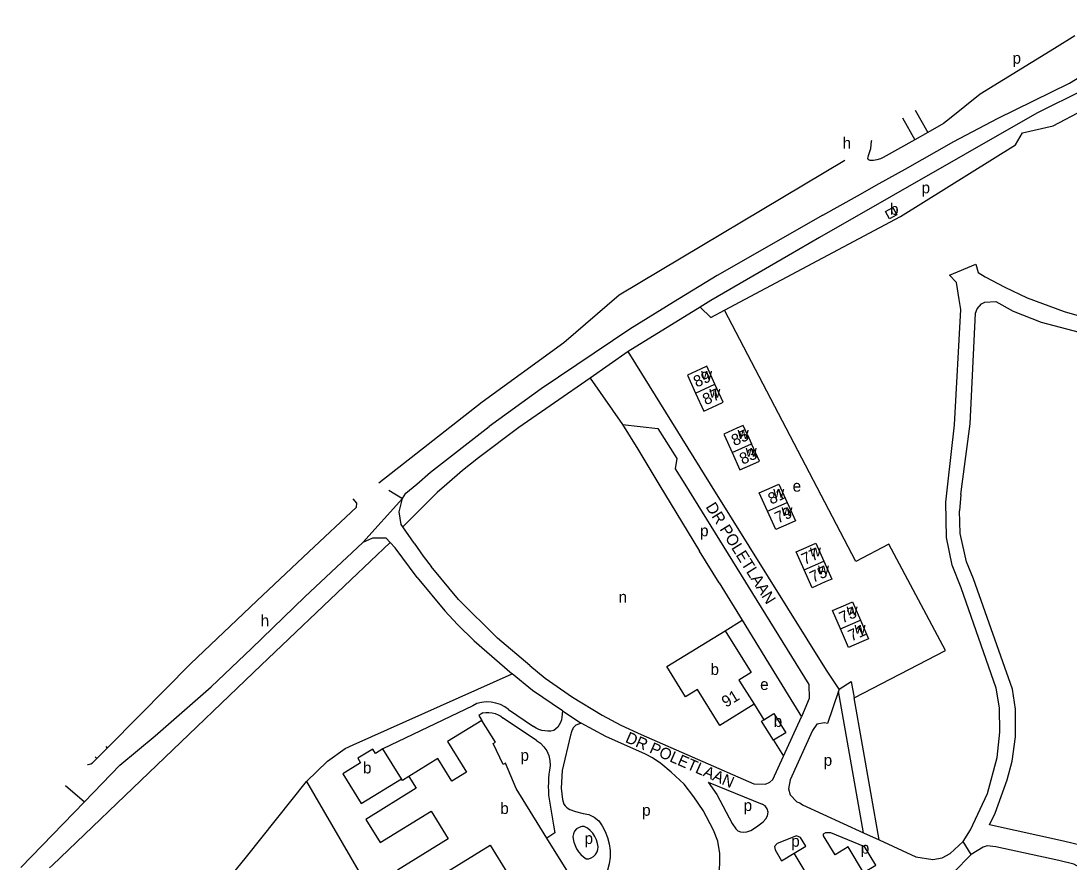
# Model space of a CAD drawing. Extents: x 158142 to 159655, y 385262 to 387204.
# Drawn here: x 158355.3 to 158722.6, y 386850.2 to 387145.1 of the extents above; entities that cross this region are included whole.
import ezdxf

# ---------------------------------------------------------------- set-up
doc = ezdxf.new("R2010")
doc.units = 0
for name, color, linetype in [('BLT_Basislijn', 7, 'Continuous'), ('BLT_Bebouwing', 7, 'Continuous'), ('BLT_Centroide', 7, 'Continuous'), ('BLT_Huisnummer', 7, 'Continuous'), ('BLT_Onderverdeling_panden', 7, 'Continuous'), ('BLT_Straatnaam_verkleind', 7, 'Continuous'), ('BLT_Vlakafsluiter', 7, 'Continuous')]:
    doc.layers.add(name, color=color, linetype=linetype)

msp = doc.modelspace()

# ---------------------------------------------------------------- linework, layer by layer
at = {"layer": 'BLT_Basislijn'}
for p, q in [((158668.7, 387113.83), (158673.07, 387105.98)), ((158664.2, 387111.11), (158668.54, 387103.46)), ((158668.54, 387103.46), (158657.46, 387097.25)), ((158624.3, 387062.87), (158597.06, 387047.07)), ((158597.06, 387047.07), (158593.31, 387044.75)), ((158593.31, 387044.75), (158568.1, 387029.18)), ((158647.81, 386955.65), (158601.87, 387043.7)), ((158568.1, 387029.18), (158554.76, 387019.92)), ((158575.58, 387017.14), (158568.1, 387029.18)), ((158554.76, 387019.92), (158529.78, 387002.58)), ((158554.76, 387019.92), (158566.14, 387003.6)), ((158596.96, 386982.75), (158575.58, 387017.14)), ((158566.14, 387003.6), (158578.5, 387002.22)), ((158566.14, 387003.6), (158571.44, 386995.01)), ((158571.44, 386995.01), (158578.85, 386982.75)), ((158578.85, 386982.75), (158593.07, 386959.23)), ((158684.65, 386979.06), (158685.14, 386982.75)), ((158684.65, 386979.06), (158684.23, 386973.41)), ((158493.12, 386962.04), (158489.16, 386967.74)), ((158599.96, 386948.18), (158593.07, 386959.23)), ((158599.96, 386948.18), (158608.05, 386934.99)), ((158602.06, 386931.34), (158608.05, 386934.99)), ((158608.05, 386934.99), (158617.27, 386919.95)), ((158617.27, 386919.95), (158628.83, 386901.11)), ((158641.77, 386910.13), (158637.96, 386898.8)), ((158642.03, 386910.9), (158641.77, 386910.13)), ((158650.51, 386860.51), (158641.77, 386910.13)), ((158656.03, 386857.97), (158647.27, 386907.76)), ((158612.17, 386905.54), (158615.56, 386900.12)), ((158396.89, 386901.68), (158385.54, 386890.21)), ((158517.13, 386902.5), (158515.7, 386901.64)), ((158515.7, 386901.64), (158516.78, 386899.9)), ((158535.92, 386892.82), (158524.32, 386900.73)), ((158526.18, 386903.69), (158534.91, 386897.78)), ((158545, 386903.25), (158551.64, 386898.89)), ((158622.54, 386887.32), (158628.83, 386901.11)), ((158549.76, 386898.23), (158548.84, 386897.27)), ((158551.64, 386898.89), (158549.76, 386898.23)), ((158547.87, 386894.73), (158544.99, 386882.31)), ((158619.04, 386892.93), (158622.54, 386887.32)), ((158385.54, 386890.21), (158381.83, 386886.51)), ((158385.06, 386890.71), (158385.54, 386890.21)), ((158381.28, 386887.07), (158381.83, 386886.51)), ((158381.53, 386886.17), (158381.5, 386886.13)), ((158544.99, 386882.31), (158544.6, 386876.15)), ((158455.35, 386878.49), (158485.3, 386827.07)), ((158596.09, 386878.27), (158614.99, 386870.5)), ((158544.6, 386876.15), (158545.01, 386872.12)), ((158540.34, 386872.23), (158541.91, 386863.19)), ((158545.01, 386872.12), (158545.49, 386870.48)), ((158549.63, 386867.99), (158552.28, 386867.28)), ((158542.39, 386860.42), (158539.56, 386858.66)), ((158638.94, 386860.64), (158650.86, 386855.74)), ((158650.51, 386860.51), (158656.03, 386857.97)), ((158654.05, 386807.61), (158626.22, 386853.36))]:
    msp.add_line(p, q, dxfattribs=at)
for points in [[(158656.08, 387088.12), (158665.09, 387093.2), (158682.14, 387102.8), (158697.48, 387110.9), (158722.77, 387123.25), (158758.56, 387145.1)], [(158724.65, 387139.9), (158717.53, 387135.44), (158691.44, 387119.47), (158680.62, 387110.78), (158678.6, 387109.21), (158673.07, 387105.98)], [(158601.87, 387043.7), (158663.51, 387076.57), (158703.82, 387101.71), (158706.29, 387105.85), (158716.99, 387108.3), (158738.31, 387119.52), (158746.24, 387131.78)], [(158746.24, 387131.78), (158727.74, 387120.92), (158711.33, 387112.82), (158635.07, 387069.15)], [(158673.07, 387105.98), (158668.54, 387103.46)], [(158657.46, 387097.25), (158656.47, 387096.81), (158655.24, 387096.42), (158654.08, 387096.24), (158652.87, 387096.21), (158652.47, 387096.33), (158652.21, 387096.58), (158652.08, 387096.94), (158652.14, 387097.34), (158652.31, 387097.95), (158653.07, 387100.38), (158653.35, 387102.91), (158653.48, 387103.32)], [(158480.68, 386983.16), (158516.92, 387011.54), (158545.57, 387032.33), (158564.97, 387049.05), (158644.03, 387096.29)], [(158636.25, 387077.06), (158648.47, 387083.82), (158656.08, 387088.12)], [(158636.25, 387077.06), (158599.31, 387055.86)], [(158635.07, 387069.15), (158624.3, 387062.87)], [(158680.15, 386982.75), (158682.46, 387003.56), (158684.6, 387043.95), (158684.07, 387047.47), (158683.08, 387053.45), (158680.71, 387055.94), (158689.96, 387059.86)], [(158689.96, 387059.86), (158690.74, 387056.94), (158693.14, 387055.45), (158700.11, 387051.72), (158707.9, 387047.99), (158720.81, 387043.24), (158746.32, 387035.84), (158759.77, 387029.16), (158763.61, 387026.95), (158774.11, 387016.37)], [(158599.31, 387055.86), (158583.99, 387046.46)], [(158583.99, 387046.46), (158568.67, 387037.06), (158537.53, 387016.18), (158519.39, 387002.88)], [(158593.31, 387044.75), (158597.05, 387041.13), (158601.87, 387043.7)], [(158685.14, 386982.75), (158687.96, 387003.81), (158689.75, 387042.71), (158690.33, 387044.22), (158691.93, 387045.94), (158693.02, 387046.57), (158696.92, 387046.72), (158702.97, 387043.35), (158712.86, 387039.5), (158730.6, 387034.84), (158745.14, 387030.27), (158755.08, 387025.45), (158760.74, 387022.19), (158771.37, 387011.13)], [(158493.99, 386982.75), (158498.83, 386986.91), (158519.39, 387002.88)], [(158529.78, 387002.58), (158515.61, 386991.9), (158510.02, 386987.52), (158504.51, 386982.75)], [(158578.5, 387002.22), (158585.12, 386991.69), (158584.58, 386988.13), (158587.91, 386982.75)], [(158489.01, 386977.69), (158490.21, 386979.51), (158493.99, 386982.75)], [(158504.51, 386982.75), (158501.1, 386979.81), (158489.16, 386967.74)], [(158587.91, 386982.75), (158631.34, 386912.43), (158631.5, 386907.6), (158628.83, 386901.11)], [(158642.03, 386910.9), (158637.55, 386917.48), (158596.96, 386982.75)], [(158685.49, 386857.44), (158688.04, 386861.5), (158693.99, 386874.3), (158697.34, 386886.83), (158698.37, 386895.73), (158698.24, 386904.35), (158697.02, 386911.16), (158684.72, 386946.4), (158681.66, 386954.26), (158679.6, 386964.01), (158679.44, 386976.41), (158680.15, 386982.75)], [(158396.89, 386901.68), (158414.75, 386919.69), (158437.92, 386941.81), (158456.13, 386958.95), (158472.85, 386974.67), (158472.97, 386976.09), (158471.68, 386977.52)], [(158489.16, 386967.74), (158488.55, 386968.62), (158487.8, 386973), (158489.01, 386977.69)], [(158694.72, 386863.26), (158696.7, 386867.43), (158700.85, 386879.03), (158702.59, 386885.55), (158703.78, 386894.19), (158703.78, 386903.86), (158702.74, 386910.84), (158689.07, 386949.52), (158686.68, 386955.53), (158684.46, 386965.39), (158684.23, 386973.41)], [(158484.7, 386962.23), (158483.26, 386963.74), (158478.42, 386963.74), (158475.1, 386962.23)], [(158365.31, 386848.23), (158366.35, 386849.16), (158439.42, 386919.27), (158470.86, 386949.22), (158484.7, 386962.23)], [(158475.1, 386962.23), (158454.77, 386943.25)], [(158494.09, 386949.99), (158486.47, 386960.37), (158484.7, 386962.23)], [(158493.12, 386962.04), (158496.21, 386957.48), (158499.01, 386953.89)], [(158647.27, 386907.76), (158679.26, 386924.45), (158659.44, 386961.72), (158647.81, 386955.65)], [(158533.64, 386919.09), (158522.24, 386928.72), (158508.56, 386942.27), (158499.01, 386953.89)], [(158494.09, 386949.99), (158503.8, 386938.26), (158508.25, 386933.49), (158514.13, 386927.76), (158527.41, 386916.22)], [(158389.95, 386884.22), (158402.29, 386894.48), (158421.96, 386911.72), (158436.04, 386925.08), (158454.77, 386943.25)], [(158533.64, 386919.09), (158538.97, 386914.68), (158548.56, 386908.02), (158559, 386901.74), (158565.5, 386898.28), (158572.62, 386894.91), (158612.16, 386877.6), (158616.23, 386877.57), (158617.73, 386878.24), (158618.79, 386879.12), (158622.54, 386887.32)], [(158455.35, 386878.49), (158462.68, 386885.65), (158468.94, 386889.99), (158471.67, 386891.38), (158527.41, 386916.22)], [(158545, 386903.25), (158534.49, 386910.36), (158527.41, 386916.22)], [(158642.03, 386910.9), (158646.26, 386913.48), (158647.27, 386907.76)], [(158515.06, 386905.84), (158513.61, 386905.01), (158482.13, 386889.9)], [(158526.18, 386903.69), (158524.84, 386904.64), (158523.35, 386905.42), (158521.73, 386905.98), (158520.04, 386906.31), (158518.33, 386906.39), (158516.66, 386906.22), (158515.06, 386905.84)], [(158517.13, 386902.5), (158518.19, 386902.65), (158519.29, 386902.67), (158520.39, 386902.55), (158521.46, 386902.28), (158522.5, 386901.88), (158523.46, 386901.36), (158524.32, 386900.73)], [(158545, 386903.25), (158544.85, 386901.02), (158544.66, 386900.1), (158544.35, 386899.2), (158543.91, 386898.35), (158543.37, 386897.57), (158542.73, 386896.88), (158542.02, 386896.3)], [(158542.02, 386896.3), (158540.99, 386896.14), (158539.92, 386896.1), (158538.84, 386896.19), (158537.78, 386896.41), (158536.76, 386896.76), (158535.8, 386897.22), (158534.91, 386897.78)], [(158548.84, 386897.27), (158548.66, 386896.92), (158548.5, 386896.57), (158548.35, 386896.21), (158548.21, 386895.85), (158548.08, 386895.48), (158547.97, 386895.11), (158547.87, 386894.73)], [(158574.2, 386888.04), (158560.19, 386894.3), (158551.64, 386898.89)], [(158637.96, 386898.8), (158636.82, 386899.03), (158634.2, 386898.53), (158632.68, 386896.3), (158624.82, 386879.03), (158624.29, 386875.85), (158624.85, 386873.77), (158627.12, 386871.37), (158628.24, 386871.05), (158629.19, 386870.32), (158650.51, 386860.51)], [(158535.92, 386892.82), (158537.29, 386891.88), (158538.51, 386890.67), (158539.52, 386889.21), (158540.24, 386887.57), (158540.64, 386885.85), (158540.72, 386884.12), (158540.49, 386882.48)], [(158378.6, 386884.49), (158378.88, 386884.49), (158379.82, 386884.69), (158380.39, 386885.02), (158381.09, 386885.67), (158381.83, 386886.51)], [(158588.55, 386827.21), (158591.7, 386830.27), (158595.11, 386834.66), (158597.78, 386839.54), (158599.8, 386845.67), (158600.25, 386849.45), (158600.15, 386853.26), (158599.44, 386857.59), (158598, 386861.47), (158594.4, 386868.25), (158591.12, 386873.15), (158587.7, 386877.49), (158583.18, 386881.78), (158579.53, 386884.75), (158576.62, 386886.78), (158574.2, 386888.04)], [(158389.95, 386884.22), (158377.52, 386871.37)], [(158540.49, 386882.48), (158540.31, 386881.03), (158540.17, 386879.57), (158540.1, 386878.1), (158540.07, 386876.63), (158540.11, 386875.16), (158540.2, 386873.69), (158540.34, 386872.23)], [(158405.76, 386799.46), (158404, 386805.94), (158403.45, 386811.11), (158403.75, 386814.36), (158434.32, 386852.05), (158455.35, 386878.49)], [(158491.24, 386880.18), (158489.01, 386878.8), (158488.6, 386879.46)], [(158596.09, 386878.27), (158599.15, 386873.86), (158604.54, 386863.74), (158605.8, 386861.86), (158606.55, 386861.22), (158607.47, 386860.87), (158608.45, 386860.7), (158609.65, 386860.82), (158611.08, 386861.32), (158613.09, 386862.56), (158615.33, 386864.37), (158616.31, 386865.39), (158616.91, 386866.48), (158617.12, 386867.71), (158616.76, 386868.9), (158616.03, 386869.91), (158614.99, 386870.5)], [(158377.52, 386871.37), (158355.28, 386848.37)], [(158545.49, 386870.48), (158545.94, 386869.95), (158546.46, 386869.47), (158547.02, 386869.04), (158547.64, 386868.67), (158548.28, 386868.37), (158548.95, 386868.15), (158549.63, 386867.99)], [(158552.28, 386867.28), (158554.27, 386866.9), (158556.16, 386866), (158557.76, 386864.64), (158558.91, 386862.97)], [(158552.28, 386867.28), (158554.27, 386866.9), (158556.16, 386866), (158557.76, 386864.64), (158558.91, 386862.97)], [(158552.28, 386867.28), (158554.27, 386866.9), (158556.16, 386866), (158557.76, 386864.64), (158558.91, 386862.97)], [(158552.28, 386867.28), (158554.27, 386866.9), (158556.16, 386866), (158557.76, 386864.64), (158558.91, 386862.97)], [(158541.91, 386863.19), (158542.39, 386860.42)], [(158552.66, 386862.65), (158551.79, 386862.64), (158550.86, 386862.38), (158550, 386861.85), (158549.3, 386861.08), (158548.86, 386860.16), (158548.7, 386859.22), (158548.78, 386858.35)], [(158557.57, 386855.54), (158557.38, 386856.79), (158557, 386858.03), (158556.43, 386859.21), (158555.69, 386860.31), (158554.79, 386861.28), (158553.78, 386862.09), (158552.66, 386862.65)], [(158558.91, 386862.97), (158559.99, 386860.98), (158560.84, 386858.83), (158561.41, 386856.57), (158561.71, 386854.24), (158561.71, 386851.91), (158561.43, 386849.62), (158560.88, 386847.42)], [(158650.56, 386846.6), (158645.11, 386855.54), (158640.56, 386852.77), (158636.49, 386859.45), (158636.56, 386860.12), (158637.37, 386860.61), (158638.94, 386860.64)], [(158740.75, 386841.06), (158733.89, 386850.93), (158730.75, 386853.84), (158726.94, 386856.05), (158720.61, 386857.61), (158694.72, 386863.26)], [(158548.78, 386858.35), (158549.05, 386857.17), (158549.47, 386856.01), (158550.02, 386854.9), (158550.7, 386853.85), (158551.49, 386852.9), (158552.38, 386852.05), (158553.35, 386851.32)], [(158656.03, 386857.97), (158668.93, 386852.03), (158674.82, 386851.13), (158678.1, 386851.74), (158680.96, 386853.27), (158685.49, 386857.44)], [(158553.35, 386851.32), (158554.23, 386851.41), (158555.12, 386851.71), (158555.96, 386852.22), (158556.67, 386852.93), (158557.18, 386853.76), (158557.48, 386854.66), (158557.57, 386855.54)], [(158650.56, 386846.6), (158654.84, 386849.2), (158650.86, 386855.74)], [(158693.92, 386823.99), (158682.07, 386843.09), (158681.86, 386843.92), (158682.12, 386846.62), (158688.28, 386852.84)], [(158731.6, 386841.96), (158728.58, 386846.31), (158726.56, 386848.18), (158724.3, 386849.49), (158719.03, 386850.79), (158696.95, 386855.61), (158693.92, 386855.92), (158692.49, 386855.5), (158688.28, 386852.84)]]:
    msp.add_lwpolyline(points, dxfattribs=at)
msp.add_lwpolyline([(158626.22, 386853.36), (158630.31, 386855.85), (158628.46, 386858.89), (158627.1, 386859.46), (158620.24, 386856.69), (158619.39, 386855.68), (158619.56, 386854.52), (158621.82, 386850.68)], close=True, dxfattribs=at)
at = {"layer": 'BLT_Bebouwing'}
for p, q in [((158601.7, 387000), (158604.46, 386993.84)), ((158609.91, 387000), (158611.3, 386996.91)), ((158602.06, 386931.34), (158611.12, 386916.66)), ((158607.12, 386913.62), (158612.17, 386905.54)), ((158614.85, 386899.68), (158615.56, 386900.12)), ((158619.04, 386892.93), (158614.85, 386899.68))]:
    msp.add_line(p, q, dxfattribs=at)
msp.add_lwpolyline([(158660.81, 387079.73), (158662.26, 387077.17), (158659.69, 387075.72), (158658.24, 387078.28)], close=True, dxfattribs=at)
for points in [[(158598.45, 387017.74), (158595.58, 387024.04), (158593.37, 387023.03), (158588.82, 387020.95), (158591.69, 387014.66)], [(158591.69, 387014.66), (158594.56, 387008.36), (158599.11, 387010.44), (158601.33, 387011.45), (158598.45, 387017.74)], [(158609.91, 387000), (158608.42, 387003.33), (158606.14, 387002.31), (158601.58, 387000.26), (158601.7, 387000)], [(158604.46, 386993.84), (158607.22, 386987.69), (158611.78, 386989.73), (158614.06, 386990.75), (158611.3, 386996.91)], [(158616.9, 386973.22), (158614.02, 386979.67), (158618.58, 386981.71), (158620.92, 386982.75), (158623.8, 386976.31)], [(158623.8, 386976.31), (158626.68, 386969.87), (158624.35, 386968.82), (158619.78, 386966.78), (158616.9, 386973.22)], [(158629.74, 386952.68), (158626.92, 386958.98), (158631.48, 386961.02), (158633.78, 386962.05), (158636.6, 386955.75)], [(158636.6, 386955.75), (158639.43, 386949.45), (158637.13, 386948.42), (158632.57, 386946.38), (158629.74, 386952.68)], [(158642.5, 386931.99), (158639.73, 386938.48), (158644.33, 386940.45), (158646.74, 386941.48), (158649.51, 386934.98)], [(158649.51, 386934.98), (158652.28, 386928.48), (158649.87, 386927.45), (158645.27, 386925.49), (158642.5, 386931.99)], [(158592.41, 386910.77), (158588.18, 386908.2), (158581.66, 386918.75), (158602.06, 386931.34)], [(158611.12, 386916.66), (158606.87, 386914.04), (158607.12, 386913.62)], [(158612.17, 386905.54), (158600.2, 386898.15), (158592.41, 386910.77)], [(158615.56, 386900.12), (158619.1, 386902.32), (158623.29, 386895.56), (158619.04, 386892.93)], [(158516.78, 386899.9), (158504.75, 386892.44), (158511.36, 386881.78), (158506.27, 386878.62), (158501.39, 386886.48), (158491.24, 386880.18)], [(158539.56, 386858.66), (158528.79, 386876.02), (158525.08, 386884.85), (158524.26, 386884.42), (158520.74, 386891.76), (158521.52, 386892.26), (158516.78, 386899.9)], [(158482.13, 386889.9), (158479.52, 386888.28), (158478.55, 386889.85), (158473.33, 386886.61), (158474.3, 386885.05), (158468.04, 386881.16)], [(158488.6, 386879.46), (158482.13, 386889.9)], [(158468.04, 386881.16), (158474.51, 386870.73), (158488.6, 386879.46)], [(158491.24, 386880.18), (158493.79, 386876.08), (158476.17, 386865.15), (158481.2, 386857.05), (158498.99, 386868.08), (158505.02, 386858.34), (158487.29, 386847.34), (158492.27, 386839.2), (158519.66, 386856.18), (158525.88, 386846.15), (158517.48, 386840.94), (158526.73, 386826.02)], [(158570.34, 386833.65), (158560.86, 386840.39), (158553.66, 386835.92), (158539.56, 386858.66)]]:
    msp.add_lwpolyline(points, dxfattribs=at)
at = {"layer": 'BLT_Onderverdeling_panden'}
for p, q in [((158591.69, 387014.66), (158598.45, 387017.74)), ((158604.46, 386993.84), (158611.3, 386996.91)), ((158616.9, 386973.22), (158623.8, 386976.31)), ((158629.74, 386952.68), (158636.6, 386955.75)), ((158642.5, 386931.99), (158649.51, 386934.98))]:
    msp.add_line(p, q, dxfattribs=at)
at = {"layer": 'BLT_Vlakafsluiter'}
for p, q in [((158475.1, 386962.23), (158489.01, 386977.69)), ((158484.18, 386980.66), (158489.01, 386977.69)), ((158370.89, 386877.07), (158377.52, 386871.37)), ((158688.28, 386852.84), (158685.49, 386857.44))]:
    msp.add_line(p, q, dxfattribs=at)

# ---------------------------------------------------------------- texts
at = {"layer": 'BLT_Centroide'}
for s, p in [('p', (158702.75, 387130.11)), ('h', (158643.23, 387100.3)), ('p', (158670.88, 387084.67)), ('b', (158659.85, 387077.16)), ('w', (158593.63, 387019.34)), ('w', (158596.51, 387013.06)), ('w', (158606.44, 386998.59)), ('w', (158609.26, 386992.31)), ('w', (158618.91, 386978)), ('e', (158625.71, 386980.08)), ('w', (158621.8, 386971.53)), ('p', (158593.27, 386964.44)), ('w', (158631.76, 386957.38)), ('w', (158634.59, 386951.06)), ('n', (158564.69, 386941.16)), ('h', (158439.29, 386932.91)), ('w', (158644.62, 386936.72)), ('w', (158647.39, 386930.25)), ('b', (158596.92, 386915.81)), ('e', (158614.32, 386910.56)), ('b', (158619.08, 386897.62)), ('b', (158475.13, 386881.31)), ('p', (158530.33, 386885.71)), ('p', (158636.59, 386883.97)), ('b', (158523.25, 386867.08)), ('p', (158608.54, 386868.14)), ('p', (158572.96, 386866.46)), ('p', (158552.77, 386856.57)), ('p', (158625.21, 386855.6)), ('p', (158649.59, 386853.19))]:
    msp.add_text(s, height=4, dxfattribs=at).set_placement(p)
at = {"layer": 'BLT_Huisnummer'}
for s, rotation, p in [('89', 24.5302, (158592.06, 387016.54)), ('87', 24.5302, (158595.27, 387010.34)), ('85', 24.5302, (158605.33, 386995.98)), ('83', 24.5302, (158608.21, 386989.48)), ('81', 24.5302, (158618.19, 386975.5)), ('79', 24.5302, (158620.56, 386968.87)), ('77', 24.5302, (158629.89, 386954.35)), ('75', 24.5302, (158632.84, 386948.08)), ('73', 24.5302, (158643.16, 386933.85)), ('71', 24.5302, (158646.28, 386927.5)), ('91', 31.4443, (158602.37, 386904.29))]:
    msp.add_text(s, height=4, rotation=rotation, dxfattribs=at).set_placement(p)
at = {"layer": 'BLT_Straatnaam_verkleind'}
for rotation, p in [(302.007, (158595.1, 386974.77)), (336.407, (158566.79, 386892.39))]:
    msp.add_text('DR POLETLAAN', height=4, rotation=rotation, dxfattribs=at).set_placement(p)

doc.saveas('drawing.dxf')
